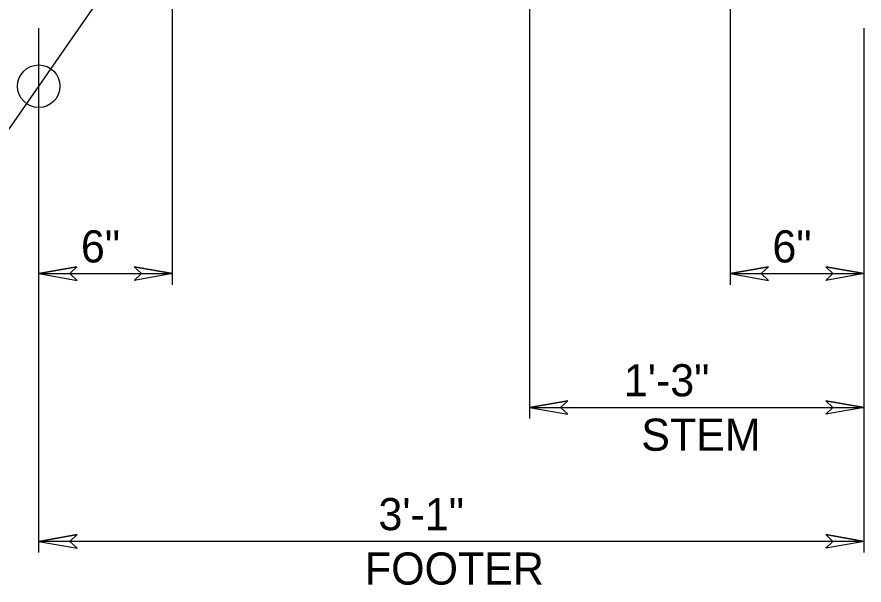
# Model space of a CAD drawing. Extents: x -26.46 to -19.21, y -3.62 to 6.25.
# Drawn here: x -23.781 to -22.199, y 0.916 to 1.977 of the extents above; entities that cross this region are included whole.
import ezdxf

# ---------------------------------------------------------------- set-up
doc = ezdxf.new("R2010")
doc.units = 0
for name, color, linetype in [('ANNO-WOUT', 7, 'Continuous'), ('DETL-DIMS', 7, 'Continuous'), ('Level 10', 7, 'Continuous'), ('Level 12', 7, 'Continuous')]:
    doc.layers.add(name, color=color, linetype=linetype)

msp = doc.modelspace()

# ---------------------------------------------------------------- linework, layer by layer
at = {"layer": 'ANNO-WOUT'}
msp.add_circle((-23.7404, 1.8477), 0.0397, dxfattribs=at)
at = {"layer": 'DETL-DIMS'}
for p, q in [((-23.7404, 1.4979), (-23.669, 1.5104)), ((-23.669, 1.5104), (-23.6824, 1.4979)), ((-23.4904, 1.4979), (-23.5619, 1.5104)), ((-23.5619, 1.5104), (-23.5484, 1.4979)), ((-22.4488, 1.4979), (-22.3773, 1.5104)), ((-22.3773, 1.5104), (-22.3908, 1.4979)), ((-22.1988, 1.4979), (-22.2702, 1.5104)), ((-22.2702, 1.5104), (-22.2568, 1.4979)), ((-23.7404, 1.4979), (-23.6689, 1.4852)), ((-23.6824, 1.4979), (-23.6689, 1.4852)), ((-23.4904, 1.4979), (-23.5619, 1.4852)), ((-23.5484, 1.4979), (-23.5619, 1.4852)), ((-22.4488, 1.4979), (-22.3773, 1.4852)), ((-22.3908, 1.4979), (-22.3773, 1.4852)), ((-22.1988, 1.4979), (-22.2703, 1.4852)), ((-22.2568, 1.4979), (-22.2703, 1.4852)), ((-22.8238, 1.2479), (-22.7523, 1.2604)), ((-22.7523, 1.2604), (-22.7658, 1.2479)), ((-22.1988, 1.2479), (-22.2702, 1.2604)), ((-22.2702, 1.2604), (-22.2568, 1.2479)), ((-22.8238, 1.2479), (-22.7523, 1.2352)), ((-22.7658, 1.2479), (-22.7523, 1.2352)), ((-22.1988, 1.2479), (-22.2703, 1.2352)), ((-22.2568, 1.2479), (-22.2703, 1.2352)), ((-23.7404, 0.9979), (-23.6689, 1.0104)), ((-23.7404, 0.9979), (-23.6689, 0.9852)), ((-23.6689, 1.0104), (-23.6824, 0.9979)), ((-23.6824, 0.9979), (-23.6689, 0.9852)), ((-22.1988, 0.9979), (-22.2703, 0.9852)), ((-22.2568, 0.9979), (-22.2703, 0.9852)), ((-22.1988, 0.9979), (-22.2702, 1.0104)), ((-22.2702, 1.0104), (-22.2568, 0.9979))]:
    msp.add_line(p, q, dxfattribs=at)
for points in [[(-23.669, 1.5104), (-23.7404, 1.4979), (-23.6689, 1.4852), (-23.6824, 1.4979)], [(-23.5619, 1.5104), (-23.4904, 1.4979), (-23.5619, 1.4852), (-23.5484, 1.4979)], [(-22.3773, 1.5104), (-22.4488, 1.4979), (-22.3773, 1.4852), (-22.3908, 1.4979)], [(-22.2702, 1.5104), (-22.1988, 1.4979), (-22.2703, 1.4852), (-22.2568, 1.4979)], [(-22.7523, 1.2604), (-22.8238, 1.2479), (-22.7523, 1.2352), (-22.7658, 1.2479)], [(-22.2702, 1.2604), (-22.1988, 1.2479), (-22.2703, 1.2352), (-22.2568, 1.2479)], [(-23.6689, 1.0104), (-23.7404, 0.9979), (-23.6689, 0.9852), (-23.6824, 0.9979)], [(-22.2702, 1.0104), (-22.1988, 0.9979), (-22.2703, 0.9852), (-22.2568, 0.9979)]]:
    msp.add_lwpolyline(points, close=True, dxfattribs=at)
at = {"layer": 'Level 10'}
for p, q in [((-22.4488, 3.373), (-22.4488, 1.4771)), ((-24.0188, 1.4469), (-23.1902, 2.64)), ((-23.4904, 1.4771), (-23.4904, 2.623)), ((-22.8238, 2.623), (-22.8238, 1.2271)), ((-23.7404, 0.9771), (-23.7404, 1.9563)), ((-22.1988, 0.9771), (-22.1988, 1.9563)), ((-23.7404, 1.4979), (-23.4904, 1.4979)), ((-22.4488, 1.4979), (-22.1988, 1.4979)), ((-22.8238, 1.2479), (-22.1988, 1.2479)), ((-22.1988, 0.9979), (-23.7404, 0.9979))]:
    msp.add_line(p, q, dxfattribs=at)

# ---------------------------------------------------------------- texts
at = {"layer": 'Level 12'}
for s, p in [('6"', (-23.6616, 1.5187)), ('6"', (-22.3699, 1.5187)), ('1\'-3"', (-22.6474, 1.2687)), ('STEM', (-22.6149, 1.1671)), ('3\'-1"', (-23.1058, 1.0187)), ('FOOTER', (-23.1311, 0.9171))]:
    msp.add_text(s, height=0.06001, dxfattribs=at).set_placement(p)

doc.saveas('drawing.dxf')
